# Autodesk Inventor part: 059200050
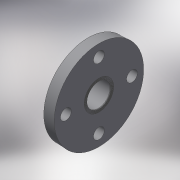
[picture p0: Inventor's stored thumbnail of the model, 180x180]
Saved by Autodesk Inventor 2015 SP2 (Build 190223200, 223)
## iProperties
Created: 2017-10
Part Number: 059200050
Material: Generic
Description: PLASSON FIXED FLANGE-CEM PVC 50
Document SubType Name: Modeling
Designer: KIM
Mass: 246.107 g
Surface Area: 487.33 cm^2
Volume: 246.107 cm^3
Density: 1 g/cm^3
Appearance: Default
Author: KIM
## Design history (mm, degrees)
derived "059200.ipt"
feature "Solid1::059200.ipt"
tag "TaggingFeature1"
body "Solid1"
other parameters: "d0" = 32, "d3" = 148.5, "d14" = 18, "d15" = 55, "d16" = 32, "d17" = 0, "d19" = 360 deg, "d21" = 31, "d23" = 47.5, "d25" = 0.5, "d26" = 0.75, "d27" = 0.75, "d28" = 0.75, "d29" = 0.75, "d30" = 0.75, "d31" = 0.75, "d32" = 0.3, "d33" = 0, "d34" = 16, "H_" = 32, "S_" = 18, "l_" = 31, "H_1" = 16
